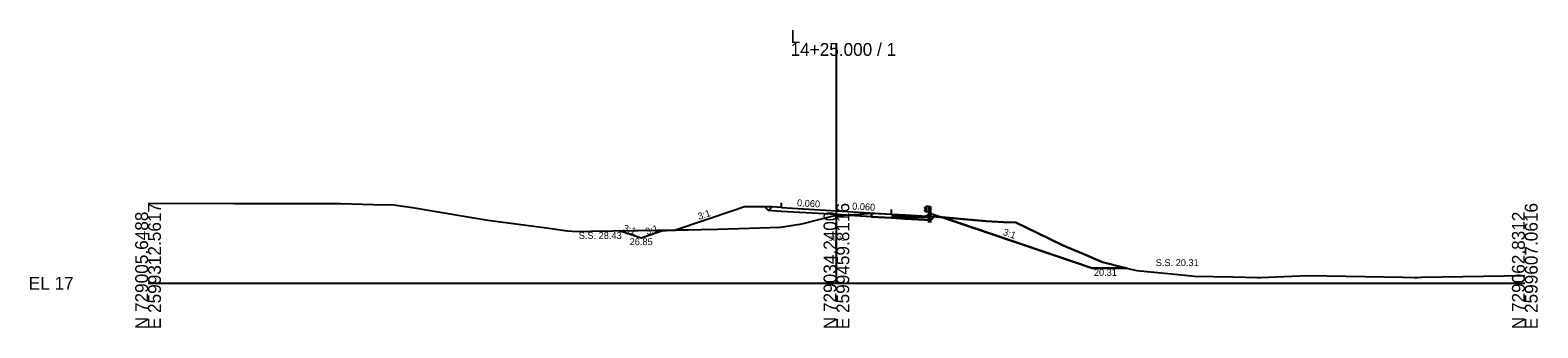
# Model space of a CAD drawing. Extents: x -26 to 3303, y -10 to 9555.
# Drawn here: x -25.7 to 302.8, y 8490.3 to 8555.1 of the extents above; entities that cross this region are included whole.
import ezdxf

# ---------------------------------------------------------------- set-up
doc = ezdxf.new("R2010")
doc.units = 0
for name, color, linetype in [('Exist Cross Section Cell', 7, 'Continuous'), ('Exist XS Center Line Elevation Label', 7, 'Continuous'), ('Exist XS Ground Line', 7, 'Continuous'), ('Prop XS Ditch Slope Text', 7, 'Continuous'), ('Prop XS Ditch Standard Text', 7, 'Continuous'), ('Prop XS Dump Level', 7, 'Continuous'), ('Prop XS Earthwork Shape', 7, 'Continuous'), ('Prop XS EOT Tick Mark', 7, 'Continuous'), ('Prop XS Finish Grade', 7, 'Continuous'), ('Prop XS Finish Grade Earthwork', 7, 'Continuous'), ('Prop XS Finish Grade Paved Shoulder', 7, 'Continuous'), ('Prop XS Finish Grade Pavement', 7, 'Continuous'), ('Prop XS Pvmt Edge Slope', 7, 'Continuous'), ('Prop XS SE Text', 7, 'Continuous'), ('Prop XS Side Slope Text', 7, 'Continuous'), ('Prop XS SS Elevation Text', 7, 'Continuous'), ('Prop XS Subgrade Earthwork', 7, 'Continuous'), ('Typical Curb CELL', 7, 'Continuous'), ('Typical Guardrail CELL', 7, 'Continuous')]:
    doc.layers.add(name, color=color, linetype=linetype)

msp = doc.modelspace()

# ---------------------------------------------------------------- linework, layer by layer
at = {"layer": 'Exist Cross Section Cell'}
for p, q in [((150, 8500), (150, 8552.32)), ((166.96, 8513.93), (166.99, 8514.35)), ((0, 8500), (150, 8500)), ((150, 8500), (300, 8500))]:
    msp.add_line(p, q, dxfattribs=at)
msp.add_lwpolyline([(166.99, 8514.35), (166.96, 8513.93), (170.56, 8513.72), (170.01, 8514.27)], close=True, dxfattribs=at)
at = {"layer": 'Exist XS Ground Line'}
msp.add_lwpolyline([(0, 8517.44), (18.86, 8517.36), (31.57, 8517.38), (34.82, 8517.37), (41.91, 8517.37), (49.12, 8517.19), (53.53, 8517.08), (57.59, 8516.53), (69.65, 8514.48), (74.01, 8513.76), (86.8, 8512.07), (91.33, 8511.45), (93.59, 8511.3), (96.42, 8511.36), (111.04, 8511.54), (120.54, 8511.69), (124.13, 8511.82), (137.78, 8512.23), (142.44, 8512.95), (146.43, 8513.93), (149.36, 8514.7), (150, 8514.75), (155.18, 8515.09), (157.62, 8515.27), (165.06, 8514.89), (169.87, 8514.64), (170.84, 8514.56), (182.61, 8513.53), (186.41, 8513.33), (189.11, 8513.23), (193.72, 8511.02), (199.43, 8508.21), (203.73, 8506.39), (207.96, 8504.6), (213.15, 8503.33), (215.43, 8502.82), (225.98, 8501.78), (228.02, 8501.58), (236.4, 8501.38), (241.71, 8501.24), (242.42, 8501.26), (252.7, 8501.67), (273.47, 8501.35), (275.92, 8501.3), (276.6, 8501.29), (277.5, 8501.31), (300, 8501.67)], dxfattribs=at)
at = {"layer": 'Prop XS Dump Level'}
for p, q in [((138, 8516.5), (150, 8515.78)), ((150, 8515.78), (162, 8515.06))]:
    msp.add_line(p, q, dxfattribs=at)
at = {"layer": 'Prop XS Earthwork Shape'}
for points in [[(127.64, 8515.84), (114.93, 8511.6), (120.54, 8511.69), (124.13, 8511.82), (137.78, 8512.23), (142.44, 8512.95), (146.43, 8513.93), (149.36, 8514.7), (150, 8514.75), (151.6, 8514.85), (150, 8514.95), (138, 8515.67), (136, 8515.79), (135.21, 8515.84), (134.43, 8516.62), (130, 8516.62)], [(120.54, 8511.69), (124.13, 8511.82), (137.78, 8512.23), (142.44, 8512.95), (146.43, 8513.93), (149.36, 8514.7), (150, 8514.75), (151.6, 8514.85), (150, 8514.95), (138, 8515.67), (136, 8515.79), (135.21, 8515.84), (134.43, 8516.62), (130, 8516.62), (127.64, 8515.84), (114.93, 8511.6)], [(155.18, 8515.09), (157.62, 8515.27), (157.62, 8514.49), (151.6, 8514.85)], [(155.18, 8515.09), (157.62, 8515.27), (157.62, 8514.49), (151.6, 8514.85)], [(165.06, 8514.89), (169.87, 8514.64), (170.84, 8514.56), (171.36, 8514.52), (170.56, 8513.72), (164.89, 8514.06), (164, 8514.11), (162, 8514.23), (157.62, 8514.49), (157.62, 8515.27)], [(157.62, 8514.49), (157.62, 8515.27), (165.06, 8514.89), (169.87, 8514.64), (170.84, 8514.56), (171.36, 8514.52), (170.56, 8513.72), (164.89, 8514.06), (164, 8514.11), (162, 8514.23)], [(171.67, 8514.83), (173.02, 8514.37), (171.36, 8514.52)], [(171.67, 8514.83), (173.02, 8514.37), (171.36, 8514.52)], [(173.02, 8514.37), (205.72, 8503.31), (213.25, 8503.31), (213.15, 8503.33), (207.96, 8504.6), (203.73, 8506.39), (199.43, 8508.21), (193.72, 8511.02), (189.11, 8513.23), (186.41, 8513.33), (182.61, 8513.53)], [(213.25, 8503.31), (205.72, 8503.31), (173.02, 8514.37), (182.61, 8513.53), (186.41, 8513.33), (189.11, 8513.23), (193.72, 8511.02), (199.43, 8508.21), (203.73, 8506.39), (207.96, 8504.6), (213.15, 8503.33)], [(102.68, 8511.43), (111.04, 8511.54), (114.93, 8511.6), (111.93, 8511.35), (107.43, 8509.85)], [(114.93, 8511.6), (111.93, 8511.35), (107.43, 8509.85), (102.68, 8511.43), (111.04, 8511.54)]]:
    msp.add_lwpolyline(points, close=True, dxfattribs=at)
at = {"layer": 'Prop XS EOT Tick Mark'}
for p, q in [((138, 8516.5), (138, 8517.5)), ((162, 8515.06), (162, 8516.06))]:
    msp.add_line(p, q, dxfattribs=at)
at = {"layer": 'Prop XS Finish Grade'}
for p, q in [((136, 8516.62), (134.43, 8516.62)), ((170.03, 8514.95), (170.56, 8515.2)), ((170.56, 8515.2), (171.67, 8514.83))]:
    msp.add_line(p, q, dxfattribs=at)
at = {"layer": 'Prop XS Finish Grade Earthwork'}
for p, q in [((127.64, 8515.84), (114.93, 8511.6)), ((130, 8516.62), (127.64, 8515.84)), ((134.43, 8516.62), (130, 8516.62)), ((171.67, 8514.83), (205.72, 8503.31)), ((107.43, 8509.85), (102.68, 8511.43)), ((111.93, 8511.35), (107.43, 8509.85)), ((114.93, 8511.6), (111.93, 8511.35)), ((213.24, 8503.31), (205.72, 8503.31))]:
    msp.add_line(p, q, dxfattribs=at)
at = {"layer": 'Prop XS Finish Grade Paved Shoulder'}
for p, q in [((138, 8516.5), (136, 8516.62)), ((161.97, 8514.61), (166.97, 8514.31)), ((161.99, 8514.81), (166.99, 8514.51)), ((162, 8515.06), (167, 8514.76))]:
    msp.add_line(p, q, dxfattribs=at)
at = {"layer": 'Prop XS Finish Grade Pavement'}
for p, q in [((138, 8516.5), (150, 8515.78)), ((150, 8515.78), (162, 8515.06))]:
    msp.add_line(p, q, dxfattribs=at)
at = {"layer": 'Prop XS Pvmt Edge Slope'}
for p, q in [((135.21, 8515.84), (134.43, 8516.62)), ((136, 8516.62), (135.21, 8515.84)), ((170.01, 8514.27), (170.56, 8513.72)), ((170.56, 8513.72), (171.67, 8514.83))]:
    msp.add_line(p, q, dxfattribs=at)
at = {"layer": 'Prop XS Subgrade Earthwork'}
for p, q in [((135.21, 8515.84), (134.43, 8516.62)), ((136, 8515.79), (135.21, 8515.84)), ((138, 8515.67), (136, 8515.79)), ((150, 8514.95), (138, 8515.67)), ((157.62, 8514.49), (150, 8514.95)), ((157.62, 8514.49), (157.62, 8515.27)), ((157.62, 8514.49), (157.62, 8515.27)), ((157.62, 8514.49), (162, 8514.23)), ((162, 8514.23), (164, 8514.11)), ((164, 8514.11), (164.89, 8514.06)), ((164.89, 8514.06), (170.56, 8513.72)), ((170.56, 8513.72), (171.67, 8514.83))]:
    msp.add_line(p, q, dxfattribs=at)
at = {"layer": 'Typical Curb CELL'}
for p, q in [((166.99, 8514.35), (167, 8514.75)), ((170.01, 8514.27), (166.99, 8514.35)), ((167, 8514.76), (167, 8514.76)), ((167.01, 8514.76), (169.33, 8514.62)), ((167.23, 8514.49), (167.32, 8514.61)), ((167.35, 8514.5), (167.23, 8514.49)), ((167.32, 8514.61), (167.35, 8514.5)), ((167.99, 8514.42), (168.06, 8514.54)), ((168.16, 8514.46), (167.99, 8514.42)), ((168.06, 8514.54), (168.16, 8514.46)), ((168.48, 8514.46), (168.57, 8514.58)), ((168.6, 8514.46), (168.48, 8514.46)), ((168.57, 8514.58), (168.6, 8514.46)), ((169.24, 8514.39), (169.31, 8514.5)), ((169.41, 8514.43), (169.24, 8514.39)), ((169.31, 8514.5), (169.41, 8514.43)), ((169.33, 8514.62), (170.03, 8514.95)), ((169.83, 8514.62), (169.84, 8514.53)), ((169.98, 8514.57), (169.83, 8514.62)), ((169.84, 8514.53), (169.98, 8514.57)), ((170.01, 8514.27), (170.03, 8514.95))]:
    msp.add_line(p, q, dxfattribs=at)
for centre in [(167.09, 8514.58), (167.13, 8514.71), (167.49, 8514.62), (167.55, 8514.44), (167.6, 8514.41), (167.64, 8514.53), (167.71, 8514.53), (167.76, 8514.56), (167.81, 8514.44), (168, 8514.48), (168.21, 8514.46), (168.23, 8514.51), (168.24, 8514.57), (168.29, 8514.42), (168.39, 8514.46), (168.48, 8514.47), (168.6, 8514.42), (168.8, 8514.41), (168.85, 8514.38), (168.89, 8514.5), (169.01, 8514.53), (169.06, 8514.41), (169.25, 8514.45), (169.28, 8514.34), (169.46, 8514.43), (169.48, 8514.48), (169.73, 8514.44), (169.85, 8514.39), (169.95, 8514.66)]:
    msp.add_circle(centre, 0.00802, dxfattribs=at)
msp.add_arc((167.01, 8514.75), 0.0104, 86.5213, 178.5693, dxfattribs=at)
at = {"layer": 'Typical Guardrail CELL'}
for p, q in [((169.53, 8516.73), (169.24, 8516.53)), ((169.53, 8516.2), (169.24, 8516.4)), ((169.53, 8516.1), (169.24, 8515.9)), ((169.53, 8515.57), (169.24, 8515.77)), ((170.03, 8516.73), (169.53, 8516.73)), ((169.53, 8516.73), (169.53, 8515.57)), ((169.53, 8516.15), (169.53, 8516.2)), ((169.53, 8516.15), (169.53, 8516.1)), ((170.03, 8515.57), (169.53, 8515.57)), ((170.03, 8516.73), (170.03, 8514.24)), ((170.03, 8516.73), (170.53, 8516.73)), ((170.53, 8516.73), (170.53, 8514.24)), ((170.03, 8514.24), (170.53, 8514.24)), ((170.03, 8514.24), (170.03, 8513.24)), ((170.53, 8514.24), (170.53, 8513.24))]:
    msp.add_line(p, q, dxfattribs=at)
for centre, start, end in [((169.29, 8516.46), 125.003, 235.0112), ((169.29, 8515.84), 125.0059, 235.0366)]:
    msp.add_arc(centre, 0.0776, start, end, dxfattribs=at)

# ---------------------------------------------------------------- texts
at = {"layer": 'Exist Cross Section Cell'}
for s, p in [('L', (140, 8552.32)), ('14+25.000 / 1', (140, 8549.52)), ('EL 17', (-26, 8498.6))]:
    msp.add_text(s, height=2.8, dxfattribs=at).set_placement(p)
for s, p in [('E 2599312.5617', (2.8, 8490)), ('E 2599459.8116', (152.8, 8490)), ('E 2599607.0616', (302.8, 8490)), ('N 729005.6488', (0, 8490)), ('N 729034.2400', (150, 8490)), ('N 729062.8312', (300, 8490))]:
    msp.add_text(s, height=2.8, rotation=90, dxfattribs=at).set_placement(p)
at = {"layer": 'Exist XS Center Line Elevation Label'}
msp.add_text('31.75', height=1, dxfattribs=at).set_placement((148.39, 8509.25))
at = {"layer": 'Prop XS Ditch Slope Text'}
msp.add_text('3:1', height=1.5, rotation=340.5558, dxfattribs=at).set_placement((186.16, 8510.57))
at = {"layer": 'Prop XS Ditch Standard Text'}
msp.add_text('20.31', height=1.5, dxfattribs=at).set_placement((206.1, 8501.62))
at = {"layer": 'Prop XS Dump Level'}
for s, height, p in [('Case1', 0.04, (130, 8516.58)), ('Eop', 0.3, (157.62, 8514.97)), ('Eop', 0.3, (157.62, 8514.97)), ('Case1', 0.04, (170, 8514.42)), ('Case1', 0.04, (173, 8514.18))]:
    msp.add_text(s, height=height, dxfattribs=at).set_placement(p)
at = {"layer": 'Prop XS SE Text'}
for p in [(141.38, 8516.8), (153.38, 8516.08)]:
    msp.add_text('0.060', height=1.5, rotation=356.5664, dxfattribs=at).set_placement(p)
at = {"layer": 'Prop XS Side Slope Text'}
for rotation, p in [(18.4349, (120.07, 8513.8)), (341.0185, (103.38, 8511.44)), (18.4349, (108.68, 8510.48))]:
    msp.add_text('3:1', height=1.5, rotation=rotation, dxfattribs=at).set_placement(p)
at = {"layer": 'Prop XS SS Elevation Text'}
for s, p in [('S.S. 28.43', (93.84, 8509.66)), ('26.85', (104.94, 8508.31)), ('S.S. 20.31', (219.58, 8503.75))]:
    msp.add_text(s, height=1.5, dxfattribs=at).set_placement(p)

doc.saveas('drawing.dxf')
